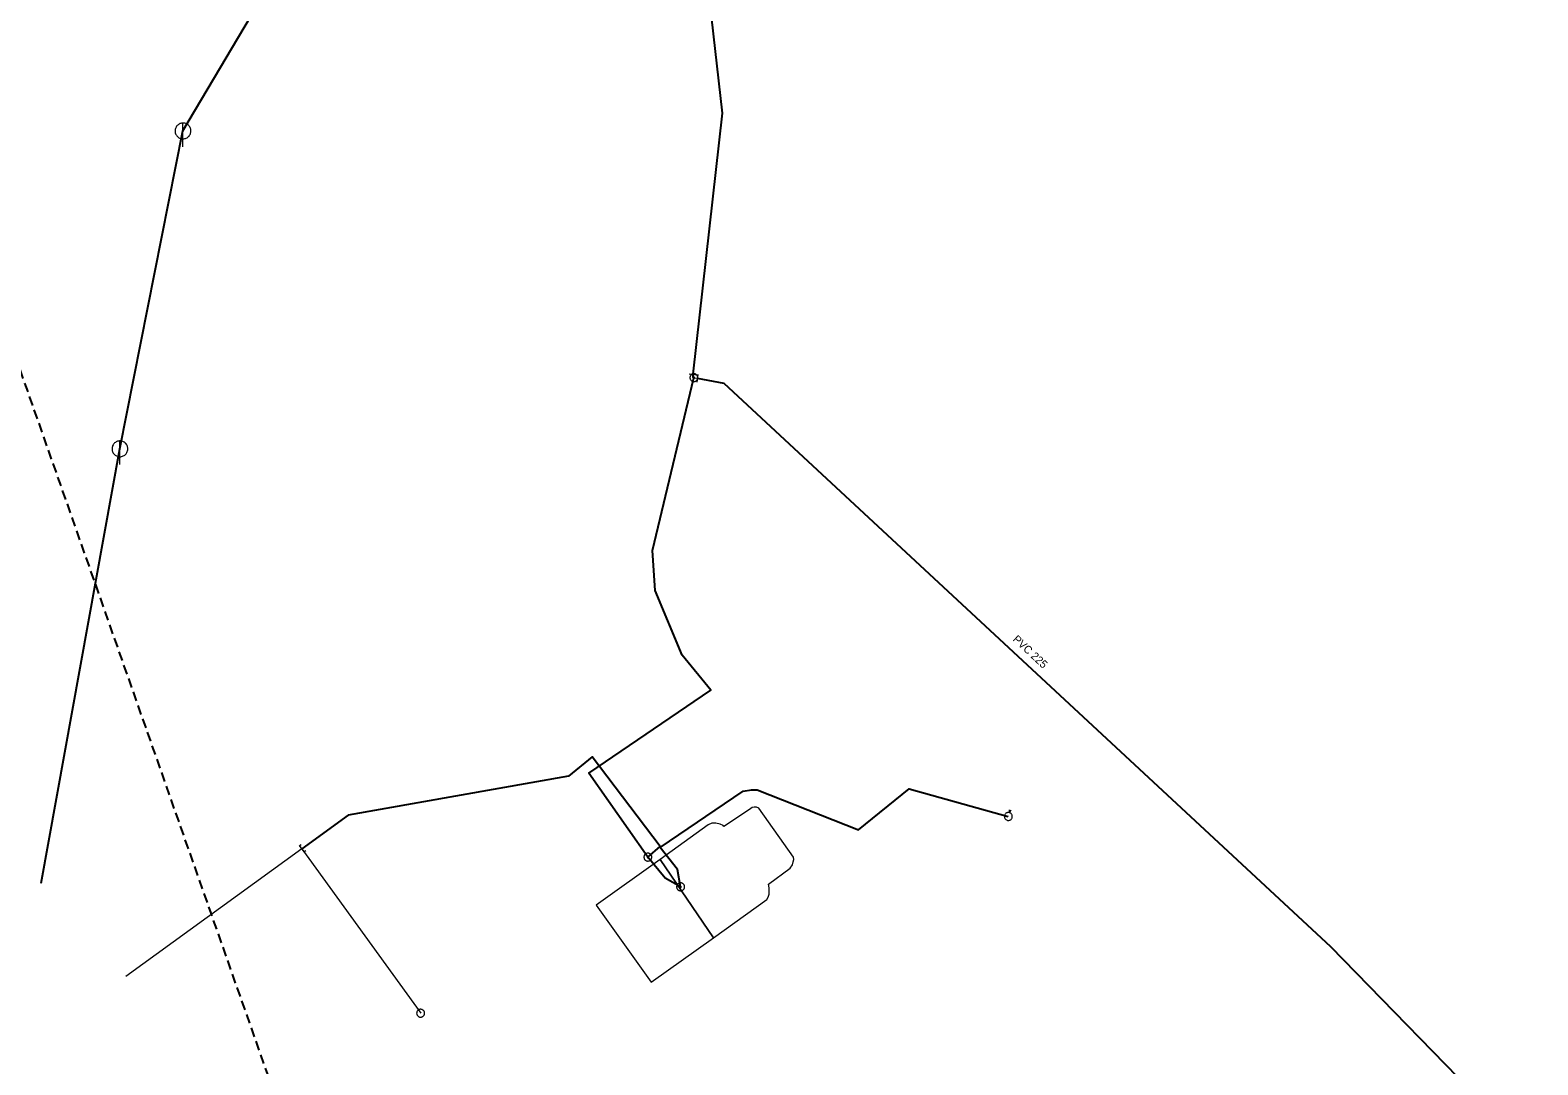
# Model space of a CAD drawing. Extents: x -659250 to -657316, y -997555 to -993684.
# Drawn here: x -658099.5 to -657908.9, y -996835.4 to -996704.6 of the extents above; entities that cross this region are included whole.
import ezdxf

# ---------------------------------------------------------------- set-up
doc = ezdxf.new("R2010")
doc.units = 0
doc.header["$LTSCALE"] = 0.4
doc.linetypes.add('MEDIUM_DASHED', pattern=[4.5, 3, -1.5])
doc.layers.add('1', color=7, linetype='Continuous')
for name, color, linetype, lineweight in [('13', 7, 'Continuous', 13), ('14', 7, 'Continuous', 25), ('17', 7, 'Continuous', 25), ('2', 7, 'Continuous', 13), ('22', 7, 'Continuous', 13), ('23', 7, 'Continuous', 13), ('34', 7, 'Continuous', 13), ('47', 7, 'Continuous', 13), ('63', 7, 'MEDIUM_DASHED', 25)]:
    doc.layers.add(name, color=color, linetype=linetype, lineweight=lineweight)

msp = doc.modelspace()

# ---------------------------------------------------------------- linework, layer by layer
at = {"layer": '13'}
for q in [(-658087.418, -996824.252), (-658050.127, -996828.92)]:
    msp.add_line((-658065.179, -996808.114), q, dxfattribs=at)
at = {"layer": '14', "lineweight": 13}
msp.add_line((-658015.613, -996748.565), (-658015.186, -996748.64), dxfattribs=at)
at = {"layer": '14'}
msp.add_lwpolyline([(-658098.14, -996812.46), (-658088.17, -996757.559), (-658080.199, -996717.37), (-658064.579, -996690.969), (-658053.649, -996672.32)], dxfattribs=at)
at = {"layer": '17'}
for points in [[(-658015.694, -996748.132), (-658012.013, -996715.116), (-658013.6, -996700.998), (-658031.362, -996648.688), (-658043.62, -996623.609), (-658054.721, -996612.745), (-658075.467, -996597.998), (-658101.14, -996577.425), (-658112.195, -996565.522), (-658140.875, -996516.98), (-658153.131, -996491.09), (-658167.719, -996475.975), (-658173.758, -996470.467)], [(-658021.431, -996809.177), (-658028.912, -996798.563), (-658013.465, -996788.068), (-658017.111, -996783.666), (-658020.489, -996775.465), (-658020.852, -996770.399), (-658015.613, -996748.565)], [(-658015.613, -996748.565), (-658015.721, -996748.55), (-658015.694, -996748.132)], [(-658015.186, -996748.64), (-658011.842, -996749.245), (-657935.128, -996820.463), (-657914.174, -996841.963)], [(-658021.431, -996809.177), (-658019.886, -996807.85), (-658028.454, -996796.511), (-658031.471, -996798.923), (-658059.3, -996803.87), (-658065.179, -996808.114)], [(-658017.294, -996812.932), (-658017.69, -996810.745), (-658019.862, -996807.969), (-658009.363, -996800.853), (-658008.326, -996800.662), (-658007.602, -996800.662), (-657994.809, -996805.727), (-657988.414, -996800.541), (-657975.863, -996804.039)], [(-658017.294, -996812.932), (-658019.259, -996811.829), (-658021.431, -996809.177)]]:
    msp.add_lwpolyline(points, dxfattribs=at)
at = {"layer": '2'}
for points in [[(-658019.859, -996809.463), (-658013.125, -996819.366), (-658006.381, -996814.537), (-658006.202, -996814.252), (-658006.092, -996813.868), (-658006.078, -996813.462), (-658006.092, -996813.061), (-658006.162, -996812.612), (-658003.453, -996810.588), (-658003.153, -996810.14), (-658003.045, -996809.77), (-658002.967, -996809.458), (-658003.037, -996809.184), (-658007.392, -996803.006), (-658007.688, -996802.868), (-658007.995, -996802.857), (-658008.23, -996802.921), (-658008.592, -996803.177), (-658011.817, -996805.32), (-658011.93, -996805.18), (-658012.271, -996805.006), (-658012.859, -996804.875), (-658013.339, -996804.903), (-658013.787, -996805.087)], [(-658027.953, -996815.239), (-658020.998, -996824.985), (-658013.125, -996819.366), (-658019.859, -996809.463)]]:
    msp.add_lwpolyline(points, close=True, dxfattribs=at)
at = {"layer": '22'}
for p, q in [((-658080.199, -996719.37), (-658080.198, -996716.37)), ((-658088.17, -996759.559), (-658088.169, -996756.559))]:
    msp.add_line(p, q, dxfattribs=at)
for points in [[(-658079.199, -996717.37), (-658079.204, -996717.261), (-658079.222, -996717.153), (-658079.252, -996717.047), (-658079.292, -996716.946), (-658079.344, -996716.849), (-658079.406, -996716.759), (-658079.478, -996716.676), (-658079.558, -996716.602), (-658079.646, -996716.536), (-658079.74, -996716.481), (-658079.84, -996716.436), (-658079.945, -996716.403), (-658080.052, -996716.381), (-658080.161, -996716.371), (-658080.271, -996716.373), (-658080.379, -996716.387), (-658080.486, -996716.412), (-658080.589, -996716.449), (-658080.687, -996716.498), (-658080.779, -996716.556), (-658080.865, -996716.625), (-658080.942, -996716.702), (-658081.011, -996716.788), (-658081.07, -996716.88), (-658081.118, -996716.978), (-658081.155, -996717.081), (-658081.181, -996717.188), (-658081.195, -996717.296), (-658081.198, -996717.406), (-658081.188, -996717.515), (-658081.167, -996717.622), (-658081.133, -996717.726), (-658081.089, -996717.826), (-658081.034, -996717.921), (-658080.968, -996718.009), (-658080.894, -996718.089), (-658080.811, -996718.161), (-658080.721, -996718.223), (-658080.625, -996718.275), (-658080.523, -996718.316), (-658080.418, -996718.346), (-658080.31, -996718.364), (-658080.2, -996718.37), (-658080.091, -996718.364), (-658079.983, -996718.346), (-658079.878, -996718.317), (-658079.776, -996718.276), (-658079.679, -996718.224), (-658079.589, -996718.162), (-658079.506, -996718.091), (-658079.431, -996718.011), (-658079.366, -996717.923), (-658079.31, -996717.829), (-658079.266, -996717.729), (-658079.232, -996717.625), (-658079.21, -996717.517), (-658079.2, -996717.408)], [(-658087.17, -996757.559), (-658087.175, -996757.45), (-658087.193, -996757.342), (-658087.223, -996757.236), (-658087.263, -996757.135), (-658087.315, -996757.038), (-658087.377, -996756.948), (-658087.449, -996756.865), (-658087.529, -996756.791), (-658087.617, -996756.725), (-658087.711, -996756.67), (-658087.811, -996756.625), (-658087.916, -996756.592), (-658088.023, -996756.57), (-658088.132, -996756.56), (-658088.242, -996756.562), (-658088.35, -996756.576), (-658088.457, -996756.601), (-658088.56, -996756.638), (-658088.658, -996756.687), (-658088.75, -996756.745), (-658088.836, -996756.814), (-658088.913, -996756.891), (-658088.982, -996756.977), (-658089.041, -996757.069), (-658089.089, -996757.167), (-658089.126, -996757.27), (-658089.152, -996757.377), (-658089.166, -996757.485), (-658089.169, -996757.595), (-658089.159, -996757.704), (-658089.138, -996757.811), (-658089.104, -996757.915), (-658089.06, -996758.015), (-658089.005, -996758.11), (-658088.939, -996758.198), (-658088.865, -996758.278), (-658088.782, -996758.35), (-658088.692, -996758.412), (-658088.596, -996758.464), (-658088.494, -996758.505), (-658088.389, -996758.535), (-658088.281, -996758.553), (-658088.171, -996758.559), (-658088.062, -996758.553), (-658087.954, -996758.535), (-658087.849, -996758.506), (-658087.747, -996758.465), (-658087.65, -996758.413), (-658087.56, -996758.351), (-658087.477, -996758.28), (-658087.402, -996758.2), (-658087.337, -996758.112), (-658087.281, -996758.018), (-658087.237, -996757.918), (-658087.203, -996757.814), (-658087.181, -996757.706), (-658087.171, -996757.597)]]:
    msp.add_lwpolyline(points, close=True, dxfattribs=at)
at = {"layer": '23'}
msp.add_lwpolyline([(-657975.383, -996804.173), (-657975.368, -996804.097), (-657975.365, -996804.02), (-657975.374, -996803.943), (-657975.395, -996803.868), (-657975.427, -996803.798), (-657975.469, -996803.733), (-657975.521, -996803.676), (-657975.581, -996803.628), (-657975.648, -996803.59), (-657975.72, -996803.562), (-657975.796, -996803.546), (-657975.873, -996803.541), (-657975.95, -996803.548), (-657976.024, -996803.568), (-657976.095, -996803.599), (-657976.161, -996803.64), (-657976.219, -996803.691), (-657976.268, -996803.751), (-657976.308, -996803.816), (-657976.338, -996803.888), (-657976.354, -996803.963), (-657976.36, -996804.04), (-657976.354, -996804.118), (-657976.336, -996804.192), (-657976.306, -996804.264), (-657976.267, -996804.33), (-657976.217, -996804.389), (-657976.158, -996804.439), (-657976.093, -996804.48), (-657976.022, -996804.51), (-657975.946, -996804.53), (-657975.869, -996804.536), (-657975.792, -996804.532), (-657975.717, -996804.516), (-657975.646, -996804.487), (-657975.579, -996804.448), (-657975.519, -996804.4), (-657975.468, -996804.342), (-657975.426, -996804.277), (-657975.394, -996804.207)], close=True, dxfattribs=at)
for points in [[(-657975.532, -996803.251), (-657975.715, -996803.523), (-657975.73, -996803.196)], [(-658049.859, -996829.315), (-658049.818, -996829.281), (-658049.781, -996829.243), (-658049.751, -996829.202), (-658049.722, -996829.158), (-658049.699, -996829.111), (-658049.682, -996829.061), (-658049.669, -996829.011), (-658049.662, -996828.96), (-658049.659, -996828.907), (-658049.662, -996828.855), (-658049.671, -996828.803), (-658049.686, -996828.752), (-658049.705, -996828.704), (-658049.729, -996828.659), (-658049.758, -996828.615), (-658049.793, -996828.574), (-658049.829, -996828.538), (-658049.871, -996828.505), (-658049.914, -996828.478), (-658049.961, -996828.454), (-658050.012, -996828.437), (-658050.062, -996828.424), (-658050.115, -996828.417), (-658050.166, -996828.413), (-658050.218, -996828.418), (-658050.27, -996828.427), (-658050.319, -996828.441), (-658050.368, -996828.461), (-658050.414, -996828.486), (-658050.458, -996828.514), (-658050.498, -996828.547), (-658050.535, -996828.585), (-658050.568, -996828.627), (-658050.595, -996828.67), (-658050.617, -996828.717), (-658050.635, -996828.766), (-658050.649, -996828.817), (-658050.657, -996828.87), (-658050.658, -996828.922)], [(-658049.871, -996828.505), (-658049.914, -996828.478), (-658049.961, -996828.454), (-658050.012, -996828.437), (-658050.062, -996828.424), (-658050.115, -996828.417), (-658050.166, -996828.413), (-658050.218, -996828.418), (-658050.27, -996828.427), (-658050.319, -996828.441), (-658050.368, -996828.461), (-658050.414, -996828.486), (-658050.458, -996828.514), (-658050.498, -996828.547), (-658050.535, -996828.585), (-658050.568, -996828.627), (-658050.595, -996828.67), (-658050.617, -996828.717), (-658050.635, -996828.766), (-658050.649, -996828.817), (-658050.657, -996828.87), (-658050.658, -996828.922), (-658050.655, -996828.973), (-658050.646, -996829.025), (-658050.633, -996829.075), (-658050.612, -996829.124), (-658050.587, -996829.17), (-658050.559, -996829.213), (-658050.525, -996829.253), (-658050.488, -996829.29), (-658050.446, -996829.323), (-658050.402, -996829.35), (-658050.355, -996829.374), (-658050.307, -996829.392), (-658050.255, -996829.404), (-658050.204, -996829.412), (-658050.152, -996829.414), (-658050.099, -996829.411), (-658050.047, -996829.402), (-658049.997, -996829.387)], [(-658050.658, -996828.922), (-658050.655, -996828.973), (-658050.646, -996829.025), (-658050.633, -996829.075), (-658050.612, -996829.124), (-658050.587, -996829.17), (-658050.559, -996829.213), (-658050.525, -996829.253), (-658050.488, -996829.29), (-658050.446, -996829.323), (-658050.402, -996829.35), (-658050.355, -996829.374), (-658050.307, -996829.392), (-658050.255, -996829.404), (-658050.204, -996829.412), (-658050.152, -996829.414), (-658050.099, -996829.411), (-658050.047, -996829.402), (-658049.997, -996829.387), (-658049.949, -996829.367), (-658049.903, -996829.343), (-658049.859, -996829.315), (-658049.818, -996829.281), (-658049.781, -996829.243), (-658049.751, -996829.202), (-658049.722, -996829.158), (-658049.699, -996829.111), (-658049.682, -996829.061), (-658049.669, -996829.011), (-658049.662, -996828.96), (-658049.659, -996828.907), (-658049.662, -996828.855), (-658049.671, -996828.803), (-658049.686, -996828.752), (-658049.705, -996828.704), (-658049.729, -996828.659), (-658049.758, -996828.615), (-658049.793, -996828.574), (-658049.829, -996828.538), (-658049.871, -996828.505)], [(-658049.997, -996829.387), (-658049.949, -996829.367), (-658049.903, -996829.343), (-658049.859, -996829.315)]]:
    msp.add_lwpolyline(points, dxfattribs=at)
at = {"layer": '34'}
for p, q in [((-658016.19, -996748.077), (-658015.197, -996748.187)), ((-658015.131, -996748.143), (-658015.241, -996749.136))]:
    msp.add_line(p, q, dxfattribs=at)
at = {"layer": '47'}
for points in [[(-658015.113, -996748.565), (-658015.116, -996748.512), (-658015.124, -996748.46), (-658015.138, -996748.411), (-658015.156, -996748.362), (-658015.18, -996748.315), (-658015.209, -996748.271), (-658015.242, -996748.23), (-658015.279, -996748.193), (-658015.319, -996748.161), (-658015.363, -996748.132), (-658015.41, -996748.107), (-658015.459, -996748.09), (-658015.509, -996748.076), (-658015.561, -996748.068), (-658015.613, -996748.065), (-658015.665, -996748.068), (-658015.717, -996748.076), (-658015.768, -996748.09), (-658015.816, -996748.107), (-658015.863, -996748.132), (-658015.907, -996748.161), (-658015.948, -996748.193), (-658015.985, -996748.23), (-658016.018, -996748.271), (-658016.046, -996748.315), (-658016.07, -996748.362), (-658016.089, -996748.411), (-658016.102, -996748.46), (-658016.11, -996748.512), (-658016.113, -996748.565), (-658016.11, -996748.617), (-658016.102, -996748.669), (-658016.089, -996748.72), (-658016.07, -996748.767), (-658016.046, -996748.815), (-658016.018, -996748.858), (-658015.985, -996748.899), (-658015.948, -996748.936), (-658015.907, -996748.97), (-658015.863, -996748.997), (-658015.816, -996749.022), (-658015.768, -996749.041), (-658015.717, -996749.053), (-658015.665, -996749.061), (-658015.613, -996749.065), (-658015.561, -996749.061), (-658015.509, -996749.053), (-658015.459, -996749.041), (-658015.41, -996749.022), (-658015.363, -996748.997), (-658015.319, -996748.97), (-658015.279, -996748.936), (-658015.242, -996748.899), (-658015.209, -996748.858), (-658015.18, -996748.815), (-658015.156, -996748.767), (-658015.138, -996748.72), (-658015.124, -996748.669), (-658015.116, -996748.617)], [(-658015.531, -996748.565), (-658015.531, -996748.556), (-658015.533, -996748.548), (-658015.535, -996748.539), (-658015.538, -996748.531), (-658015.542, -996748.524), (-658015.547, -996748.517), (-658015.552, -996748.509), (-658015.558, -996748.504), (-658015.565, -996748.499), (-658015.572, -996748.494), (-658015.58, -996748.49), (-658015.588, -996748.487), (-658015.596, -996748.485), (-658015.604, -996748.482), (-658015.613, -996748.482), (-658015.622, -996748.482), (-658015.63, -996748.485), (-658015.638, -996748.487), (-658015.646, -996748.49), (-658015.654, -996748.494), (-658015.661, -996748.499), (-658015.668, -996748.504), (-658015.674, -996748.509), (-658015.68, -996748.517), (-658015.684, -996748.524), (-658015.688, -996748.531), (-658015.691, -996748.539), (-658015.693, -996748.548), (-658015.695, -996748.556), (-658015.695, -996748.565), (-658015.695, -996748.573), (-658015.693, -996748.581), (-658015.691, -996748.59), (-658015.688, -996748.598), (-658015.684, -996748.605), (-658015.68, -996748.612), (-658015.674, -996748.62), (-658015.668, -996748.625), (-658015.661, -996748.632), (-658015.654, -996748.636), (-658015.646, -996748.639), (-658015.638, -996748.642), (-658015.63, -996748.644), (-658015.622, -996748.647), (-658015.613, -996748.647), (-658015.604, -996748.647), (-658015.596, -996748.644), (-658015.588, -996748.642), (-658015.58, -996748.639), (-658015.572, -996748.636), (-658015.565, -996748.632), (-658015.558, -996748.625), (-658015.552, -996748.62), (-658015.547, -996748.612), (-658015.542, -996748.605), (-658015.538, -996748.598), (-658015.535, -996748.59), (-658015.533, -996748.581), (-658015.531, -996748.573)], [(-658020.931, -996809.177), (-658020.934, -996809.125), (-658020.942, -996809.073), (-658020.956, -996809.023), (-658020.973, -996808.974), (-658020.998, -996808.927), (-658021.027, -996808.883), (-658021.059, -996808.843), (-658021.097, -996808.806), (-658021.137, -996808.773), (-658021.181, -996808.744), (-658021.228, -996808.72), (-658021.277, -996808.702), (-658021.326, -996808.688), (-658021.379, -996808.68), (-658021.431, -996808.677), (-658021.483, -996808.68), (-658021.535, -996808.688), (-658021.586, -996808.702), (-658021.634, -996808.72), (-658021.681, -996808.744), (-658021.725, -996808.773), (-658021.766, -996808.806), (-658021.803, -996808.843), (-658021.836, -996808.883), (-658021.864, -996808.927), (-658021.888, -996808.974), (-658021.907, -996809.023), (-658021.919, -996809.073), (-658021.928, -996809.125), (-658021.931, -996809.177), (-658021.928, -996809.229), (-658021.919, -996809.281), (-658021.907, -996809.332), (-658021.888, -996809.38), (-658021.864, -996809.427), (-658021.836, -996809.471), (-658021.803, -996809.512), (-658021.766, -996809.549), (-658021.725, -996809.582), (-658021.681, -996809.61), (-658021.634, -996809.634), (-658021.586, -996809.653), (-658021.535, -996809.666), (-658021.483, -996809.674), (-658021.431, -996809.677), (-658021.379, -996809.674), (-658021.326, -996809.666), (-658021.277, -996809.653), (-658021.228, -996809.634), (-658021.181, -996809.61), (-658021.137, -996809.582), (-658021.097, -996809.549), (-658021.059, -996809.512), (-658021.027, -996809.471), (-658020.998, -996809.427), (-658020.973, -996809.38), (-658020.956, -996809.332), (-658020.942, -996809.281), (-658020.934, -996809.229)], [(-658021.348, -996809.177), (-658021.348, -996809.168), (-658021.351, -996809.16), (-658021.353, -996809.152), (-658021.356, -996809.144), (-658021.36, -996809.136), (-658021.365, -996809.129), (-658021.37, -996809.122), (-658021.375, -996809.116), (-658021.383, -996809.111), (-658021.39, -996809.106), (-658021.397, -996809.102), (-658021.406, -996809.099), (-658021.414, -996809.097), (-658021.422, -996809.095), (-658021.431, -996809.095), (-658021.44, -996809.095), (-658021.448, -996809.097), (-658021.456, -996809.099), (-658021.464, -996809.102), (-658021.472, -996809.106), (-658021.478, -996809.111), (-658021.486, -996809.116), (-658021.492, -996809.122), (-658021.498, -996809.129), (-658021.502, -996809.136), (-658021.505, -996809.144), (-658021.509, -996809.152), (-658021.511, -996809.16), (-658021.513, -996809.168), (-658021.513, -996809.177), (-658021.513, -996809.186), (-658021.511, -996809.194), (-658021.509, -996809.202), (-658021.505, -996809.21), (-658021.502, -996809.218), (-658021.498, -996809.225), (-658021.492, -996809.232), (-658021.486, -996809.238), (-658021.478, -996809.244), (-658021.472, -996809.248), (-658021.464, -996809.252), (-658021.456, -996809.255), (-658021.448, -996809.257), (-658021.44, -996809.259), (-658021.431, -996809.259), (-658021.422, -996809.259), (-658021.414, -996809.257), (-658021.406, -996809.255), (-658021.397, -996809.252), (-658021.39, -996809.248), (-658021.383, -996809.244), (-658021.375, -996809.238), (-658021.37, -996809.232), (-658021.365, -996809.225), (-658021.36, -996809.218), (-658021.356, -996809.21), (-658021.353, -996809.202), (-658021.351, -996809.194), (-658021.348, -996809.186)], [(-658016.794, -996812.933), (-658016.797, -996812.88), (-658016.805, -996812.828), (-658016.819, -996812.779), (-658016.837, -996812.73), (-658016.861, -996812.683), (-658016.89, -996812.639), (-658016.923, -996812.598), (-658016.96, -996812.561), (-658017, -996812.529), (-658017.044, -996812.5), (-658017.091, -996812.475), (-658017.14, -996812.458), (-658017.19, -996812.444), (-658017.242, -996812.436), (-658017.294, -996812.433), (-658017.346, -996812.436), (-658017.398, -996812.444), (-658017.449, -996812.458), (-658017.497, -996812.475), (-658017.544, -996812.5), (-658017.588, -996812.529), (-658017.629, -996812.561), (-658017.666, -996812.598), (-658017.699, -996812.639), (-658017.727, -996812.683), (-658017.751, -996812.73), (-658017.77, -996812.779), (-658017.782, -996812.828), (-658017.791, -996812.88), (-658017.794, -996812.933), (-658017.791, -996812.985), (-658017.782, -996813.037), (-658017.77, -996813.088), (-658017.751, -996813.136), (-658017.727, -996813.183), (-658017.699, -996813.227), (-658017.666, -996813.267), (-658017.629, -996813.304), (-658017.588, -996813.338), (-658017.544, -996813.365), (-658017.497, -996813.39), (-658017.449, -996813.409), (-658017.398, -996813.421), (-658017.346, -996813.429), (-658017.294, -996813.433), (-658017.242, -996813.429), (-658017.19, -996813.421), (-658017.14, -996813.409), (-658017.091, -996813.39), (-658017.044, -996813.365), (-658017, -996813.338), (-658016.96, -996813.304), (-658016.923, -996813.267), (-658016.89, -996813.227), (-658016.861, -996813.183), (-658016.837, -996813.136), (-658016.819, -996813.088), (-658016.805, -996813.037), (-658016.797, -996812.985)], [(-658017.212, -996812.933), (-658017.212, -996812.924), (-658017.214, -996812.916), (-658017.216, -996812.907), (-658017.219, -996812.899), (-658017.223, -996812.892), (-658017.228, -996812.885), (-658017.233, -996812.877), (-658017.239, -996812.872), (-658017.246, -996812.867), (-658017.253, -996812.862), (-658017.261, -996812.858), (-658017.269, -996812.855), (-658017.277, -996812.853), (-658017.285, -996812.85), (-658017.294, -996812.85), (-658017.303, -996812.85), (-658017.311, -996812.853), (-658017.319, -996812.855), (-658017.327, -996812.858), (-658017.335, -996812.862), (-658017.342, -996812.867), (-658017.349, -996812.872), (-658017.355, -996812.877), (-658017.361, -996812.885), (-658017.365, -996812.892), (-658017.369, -996812.899), (-658017.372, -996812.907), (-658017.374, -996812.916), (-658017.376, -996812.924), (-658017.376, -996812.933), (-658017.376, -996812.941), (-658017.374, -996812.95), (-658017.372, -996812.958), (-658017.369, -996812.966), (-658017.365, -996812.973), (-658017.361, -996812.98), (-658017.355, -996812.988), (-658017.349, -996812.994), (-658017.342, -996813), (-658017.335, -996813.004), (-658017.327, -996813.007), (-658017.319, -996813.011), (-658017.311, -996813.012), (-658017.303, -996813.015), (-658017.294, -996813.015), (-658017.285, -996813.015), (-658017.277, -996813.012), (-658017.269, -996813.011), (-658017.261, -996813.007), (-658017.253, -996813.004), (-658017.246, -996813), (-658017.239, -996812.994), (-658017.233, -996812.988), (-658017.228, -996812.98), (-658017.223, -996812.973), (-658017.219, -996812.966), (-658017.216, -996812.958), (-658017.214, -996812.95), (-658017.212, -996812.941)]]:
    msp.add_lwpolyline(points, close=True, dxfattribs=at)
msp.add_lwpolyline([(-658064.684, -996808.368), (-658064.888, -996808.516), (-658065.469, -996807.711), (-658065.265, -996807.564)], dxfattribs=at)
at = {"layer": '63'}
msp.add_lwpolyline([(-659116.685, -993855.266), (-658551.464, -993848.288), (-658551.464, -993848.288), (-657316.352, -997490.822), (-657316.352, -997490.822), (-657839.705, -997490.822), (-657839.705, -997490.822)], close=True, dxfattribs=at)

# ---------------------------------------------------------------- texts
at = {"layer": '1'}
msp.add_text('PVC 225 ', height=1, rotation=317, dxfattribs=at).set_placement((-657975.38, -996781.751))

doc.saveas('drawing.dxf')
